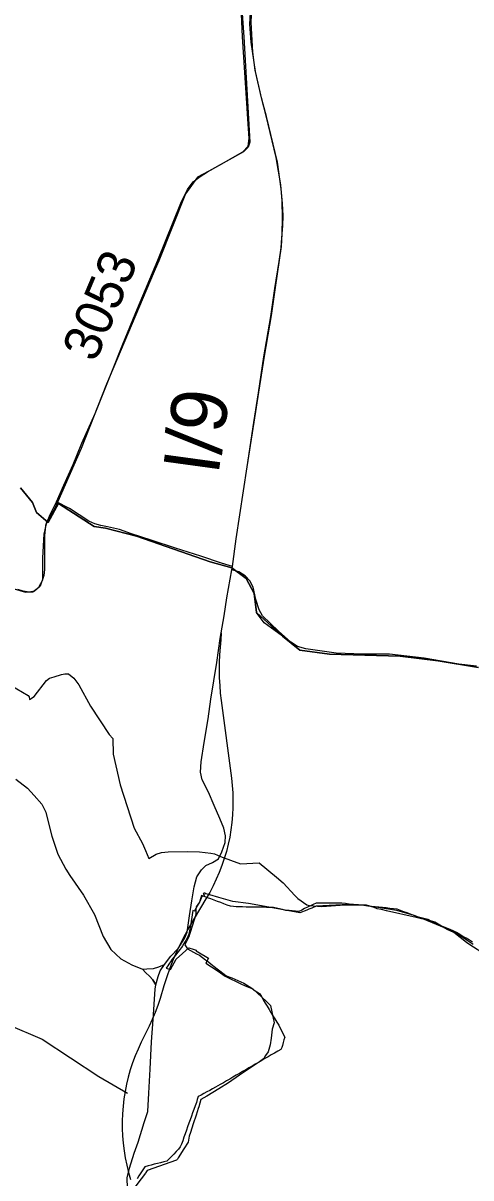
# Model space of a CAD drawing. Extents: x -789162 to -606354, y -1062736 to -945481.
# Drawn here: x -726966 to -725766, y -985051 to -981952 of the extents above; entities that cross this region are included whole.
import ezdxf

# ---------------------------------------------------------------- set-up
doc = ezdxf.new("R2010")
doc.units = 0
for name, color, linetype in [('_SIRSI VZTAHY CHKO HRANICE', 7, 'Continuous'), ('_SIRSI VZTAHY_CYKLOTRASY MISTNI S', 7, 'Continuous'), ('_SIRSI VZTAHY_CYKLOTRASY MISTNI_POPIS', 7, 'Continuous'), ('_SIRSI VZTAHY_NATURA_EVL', 7, 'Continuous'), ('_SIRSI VZTAHY_OP vodnich zdroju II stupne', 7, 'Continuous'), ('_SIRSI VZTAHY_SILNICE I TRIDY_NAVRH', 7, 'Continuous'), ('_SIRSI VZTAHY_SILNICE I TRIDY_STAV', 7, 'Continuous'), ('_SIRSI VZTAHY_SILNICE III TRIDY_STAV', 7, 'Continuous'), ('_SIRSI VZTAHY_SILNICE_STAV_POPIS', 7, 'Continuous')]:
    doc.layers.add(name, color=color, linetype=linetype)

msp = doc.modelspace()

# ---------------------------------------------------------------- linework, layer by layer
at = {"layer": '_SIRSI VZTAHY CHKO HRANICE'}
msp.add_lwpolyline([(-725726.8, -984451.8), (-725769.2, -984425.2), (-725778.1, -984418.6), (-725811.9, -984392.6), (-725829.7, -984384), (-725835.6, -984380.8), (-725862.4, -984364.8), (-725876.7, -984360.1), (-725890.2, -984357.2), (-725898.3, -984355.2), (-725912.6, -984351.8), (-725992.6, -984334), (-726005.6, -984330.9), (-726017.4, -984328.3), (-726025.6, -984325.4), (-726045.8, -984318.8), (-726067.4, -984317.5), (-726080.4, -984317), (-726093.1, -984317.2), (-726180.8, -984321.6), (-726192.3, -984326.6), (-726200, -984329.9), (-726206.2, -984332.6), (-726224.7, -984339.3), (-726288, -984327.7), (-726362.4, -984314.2), (-726404.5, -984309.4), (-726441.5, -984298.6), (-726466.1, -984291.2), (-726476.2, -984288.6), (-726478.9, -984286.5), (-726482.2, -984286.5), (-726482.3, -984286.6), (-726484, -984289.5), (-726480.4, -984290.8), (-726481.7, -984294.7), (-726481.7, -984294.7), (-726485.8, -984293.9), (-726485.9, -984294), (-726493.1, -984310.5), (-726506.9, -984334.4), (-726506.9, -984334.4), (-726506.9, -984334.5), (-726511.3, -984333.4), (-726511.8, -984333.3), (-726512.5, -984338.5), (-726514.3, -984351.1), (-726516, -984362.3), (-726517.9, -984375.4), (-726519.9, -984387.5), (-726522.2, -984396.3), (-726523.6, -984400.9), (-726525.6, -984404.7), (-726530.3, -984413.2), (-726533.7, -984419.2), (-726538.1, -984426.3), (-726539.2, -984428.1), (-726541.8, -984432.1), (-726546.4, -984437.6), (-726548.1, -984440.4), (-726561.6, -984457.5), (-726566.5, -984463.5), (-726569.4, -984468), (-726575.8, -984477.4), (-726578.6, -984481.4), (-726580.8, -984484.8), (-726582.8, -984487.9), (-726571.1, -984491.3), (-726555.6, -984463.8), (-726521.8, -984433.5), (-726510.3, -984437.2), (-726502, -984439.7), (-726502.7, -984440.9), (-726497.9, -984443.7), (-726469.8, -984460.8), (-726476.7, -984474.4), (-726443.9, -984496), (-726424.6, -984509.1), (-726381.1, -984531.2), (-726366.8, -984536.8), (-726350.8, -984543.4), (-726314.3, -984576.9), (-726302.8, -984587.8), (-726293.1, -984634.8), (-726298.3, -984651.8), (-726299.6, -984659.6), (-726301.4, -984675.4), (-726303.8, -984693.4), (-726309.8, -984712.1), (-726316.2, -984722.3), (-726321.2, -984730.6), (-726321.6, -984730.9), (-726332.9, -984738.7), (-726354.1, -984753.2), (-726386.1, -984775.1), (-726416.1, -984795.9), (-726442, -984811.6), (-726473.8, -984830.9), (-726489.5, -984840.4), (-726495.5, -984859.6), (-726497, -984864.2), (-726502.8, -984882.3), (-726510.3, -984905.6), (-726517.6, -984928.6), (-726520.8, -984939), (-726522.8, -984949.6), (-726524, -984955), (-726535.2, -984972.8), (-726550.4, -984996.3), (-726552.8, -985000.1), (-726555.2, -985003.2), (-726634.2, -985031.1), (-726637.1, -985035.9), (-726638.4, -985037.6), (-726676.1, -985086.8)], dxfattribs=at)
at = {"layer": '_SIRSI VZTAHY_CYKLOTRASY MISTNI S'}
for points in [[(-726381.6, -981889.3), (-726374.5, -981989.5), (-726358.6, -982272.2), (-726363.3, -982285.3), (-726375.7, -982298.1), (-726468.6, -982349.9), (-726498.5, -982365.5), (-726530.8, -982410.8), (-726602.7, -982590.6), (-726614.7, -982618.4), (-726742.4, -982921.4), (-726810.9, -983094), (-726873, -983236.1), (-726883.5, -983257.7), (-726902.3, -983289.5), (-726906, -983300.1), (-726908.7, -983327.7), (-726908.7, -983366.1), (-726909.2, -983418), (-726911, -983434.7), (-726920.5, -983463.4), (-726935.6, -983476.5), (-726950, -983479.2), (-726965.8, -983476.5), (-726980.3, -983471.8)], [(-726998.3, -983729.8), (-726953, -983756.6), (-726950.5, -983759.8), (-726948.8, -983767), (-726936.8, -983758.6), (-726903.9, -983715.7), (-726895.4, -983709.5), (-726882.9, -983706), (-726863, -983700), (-726854.8, -983698), (-726844.7, -983698), (-726830.5, -983709.6), (-726816.8, -983728), (-726785.7, -983785.1), (-726735.6, -983861.4), (-726725.4, -983871.5), (-726725.1, -983913.5), (-726717.8, -983944.9), (-726706, -983996.1), (-726668.9, -984112.3), (-726646.2, -984153.5), (-726638.3, -984172), (-726628.9, -984193.7), (-726609.8, -984181.9), (-726595.5, -984177.4), (-726577.8, -984175.4), (-726525.8, -984175.1), (-726493.8, -984176.1), (-726462.8, -984179.4), (-726453.5, -984181.2), (-726437.2, -984187.9), (-726383.8, -984207.7), (-726333.8, -984205.1), (-726287, -984243.9), (-726269, -984258.8), (-726238.2, -984292.6), (-726230.3, -984301.3), (-726206.2, -984318.1), (-726199.3, -984319.7), (-726166, -984322.2), (-726104.1, -984318), (-726056.8, -984318.1), (-726026.1, -984322.1), (-725976.2, -984330.1), (-725965.3, -984331.8), (-725918.6, -984345.8), (-725895.4, -984354.3), (-725822.6, -984384.6), (-725792.4, -984402.4), (-725760.2, -984423.9)]]:
    msp.add_lwpolyline(points, dxfattribs=at)
at = {"layer": '_SIRSI VZTAHY_NATURA_EVL'}
msp.add_line((-726235.9, -984334.8), (-726235.9, -984334.8), dxfattribs=at)
for points in [[(-726235.9, -984334.8), (-726244.7, -984334.2), (-726253.5, -984333.5), (-726262.3, -984332.9), (-726270.6, -984330.9), (-726278.8, -984329), (-726287.1, -984327.1), (-726295.4, -984325.1), (-726304.5, -984325), (-726313.7, -984324.8), (-726322.9, -984324.6), (-726332, -984324.4), (-726341.2, -984324.3), (-726350.4, -984324.1), (-726359.5, -984323.9), (-726368.7, -984323.8), (-726377.8, -984323.6), (-726387, -984323.4), (-726394.8, -984322.9), (-726402.6, -984322.3), (-726410.4, -984321.7), (-726419.2, -984318.4), (-726428, -984315.1), (-726436.7, -984311.9), (-726445.5, -984308.6), (-726454.2, -984305.3), (-726463, -984302), (-726471.7, -984298.8), (-726480.5, -984295.5), (-726481.2, -984295.2), (-726487.7, -984292.9), (-726490.5, -984301.9), (-726493.3, -984310.9), (-726498, -984317), (-726502.6, -984323), (-726503, -984330), (-726503.3, -984337), (-726503.6, -984343.9), (-726506.3, -984352.5), (-726509, -984361), (-726511.6, -984369.5), (-726514.3, -984378), (-726517, -984386.6), (-726519.6, -984395.1), (-726522.3, -984403.6), (-726525.7, -984410.9), (-726529.1, -984418.2), (-726532.5, -984425.6), (-726529.3, -984430.9), (-726526.1, -984436.2), (-726517.9, -984440.5), (-726509.6, -984444.8), (-726501.4, -984449), (-726493.1, -984453.2), (-726485.3, -984459.3), (-726477.6, -984465.3), (-726469.8, -984471.3), (-726462, -984477.3), (-726454.2, -984483.3), (-726446.4, -984489.3), (-726438.6, -984495.3), (-726430.8, -984501.3), (-726423.1, -984507.3), (-726414.9, -984510.7), (-726406.8, -984514.2), (-726398.7, -984517.6), (-726390.6, -984521), (-726382.5, -984524.4), (-726374.4, -984527.9), (-726367.4, -984532.5), (-726360.5, -984537.2), (-726353.6, -984541.8), (-726346.7, -984546.5), (-726339.7, -984551.2), (-726332.8, -984555.8), (-726327.7, -984564.3), (-726322.5, -984572.9), (-726317.3, -984581.4), (-726312.2, -984589.9), (-726307, -984598.4), (-726301.9, -984607), (-726296.7, -984615.5), (-726291.6, -984624), (-726286.4, -984632.5), (-726281.2, -984641.1), (-726277.2, -984649.1), (-726273.2, -984657.2), (-726269.2, -984665.2), (-726265.1, -984673.3), (-726267, -984680.5), (-726268.9, -984687.7), (-726270.8, -984694.9), (-726273.1, -984700.3), (-726275.4, -984705.7), (-726283.9, -984710.7), (-726292.5, -984715.6), (-726301.1, -984720.6), (-726309.6, -984725.6), (-726318.2, -984730.5), (-726326.8, -984735.5), (-726335.3, -984740.5), (-726343.9, -984745.5), (-726352.4, -984750.4), (-726361, -984755.4), (-726369.6, -984760.4), (-726378.1, -984765.3), (-726386.7, -984770.3), (-726395.2, -984775.3), (-726403.8, -984780.2), (-726412.4, -984785.2), (-726420.9, -984790.2), (-726429.5, -984795.2), (-726438.1, -984800.1), (-726444.2, -984803.7), (-726450.4, -984807.2), (-726458.2, -984811.4), (-726466, -984815.6), (-726473.8, -984819.8), (-726481.6, -984824.1), (-726489.4, -984828.3), (-726497.2, -984832.5), (-726499.6, -984840.2), (-726501.9, -984847.9), (-726505.3, -984857.2), (-726508.6, -984866.6), (-726511.9, -984875.9), (-726515.3, -984885.3), (-726518.6, -984894.6), (-726521.9, -984904), (-726525.3, -984913.4), (-726528.6, -984922.7), (-726531.9, -984932.1), (-726535.3, -984941.4), (-726538.6, -984950.8), (-726541.9, -984960.1), (-726545.7, -984966.9), (-726549.4, -984973.8), (-726555.7, -984980.1), (-726562.1, -984986.4), (-726568.4, -984992.7), (-726574.7, -984999.1), (-726581.1, -985005.4), (-726589.5, -985007.5), (-726597.9, -985009.7), (-726606.3, -985011.8), (-726614.7, -985013.9), (-726623.1, -985016.1), (-726631.5, -985018.2), (-726639.9, -985020.4), (-726645.1, -985028.6), (-726650.4, -985036.8), (-726655.7, -985045.1), (-726660.9, -985053.3)], [(-725761.6, -984417.7), (-725770.2, -984412.7), (-725778.8, -984407.6), (-725787.4, -984402.6), (-725796, -984397.5), (-725804.6, -984392.4), (-725813.2, -984387.4), (-725821.9, -984384), (-725830.6, -984380.7), (-725839.4, -984377.3), (-725848.1, -984374), (-725856.8, -984370.6), (-725864.9, -984366.1), (-725872.9, -984361.7), (-725880.9, -984357.2), (-725888.3, -984355.4), (-725895.6, -984353.6), (-725903, -984351.8), (-725910.3, -984350.1), (-725919.2, -984346.6), (-725928.1, -984343.2), (-725937, -984339.8), (-725945.9, -984336.4), (-725954.8, -984333), (-725963.7, -984329.6), (-725973.6, -984328.5), (-725983.4, -984327.4), (-725993.3, -984326.4), (-726003.2, -984325.3), (-726013.1, -984324.2), (-726022.9, -984323.2), (-726032.8, -984322.1), (-726042.7, -984321.1), (-726052.6, -984320), (-726062.4, -984318.9), (-726072.3, -984317.9), (-726082.2, -984316.8), (-726092.1, -984315.8), (-726101.9, -984314.7), (-726111.8, -984313.6), (-726121.7, -984313.6), (-726131.6, -984313.6), (-726141.5, -984313.6), (-726151.3, -984313.6), (-726161.2, -984313.6), (-726171.1, -984313.6), (-726181, -984313.6), (-726188.7, -984317.3), (-726196.4, -984320.9), (-726204, -984324.6), (-726211.7, -984328.2), (-726219.4, -984331.9), (-726227.1, -984335.5), (-726235.9, -984334.8)]]:
    msp.add_lwpolyline(points, dxfattribs=at)
at = {"layer": '_SIRSI VZTAHY_OP vodnich zdroju II stupne'}
for points in [[(-726973.1, -983199.3), (-726941.4, -983239), (-726930.8, -983265.4), (-726899.1, -983291.9), (-726871.3, -983241.6), (-726776, -983302.5), (-726745.6, -983307.8), (-726662.3, -983328.9), (-726465.1, -983397.7), (-726406.9, -983413.6), (-726368.6, -983442.7), (-726347.4, -983482.4), (-726340.8, -983534), (-726270.7, -983597.5), (-726224.4, -983634.5), (-726145, -983645.1), (-725955.8, -983650.4), (-725854, -983663.6), (-725745.5, -983680.8)], [(-725745.5, -983680.8), (-725854, -983663.6), (-725955.8, -983650.4), (-726145, -983645.1), (-726224.4, -983634.5), (-726270.7, -983597.5), (-726320.1, -983561.2), (-726340.8, -983534), (-726347.4, -983482.4), (-726368.6, -983442.7), (-726406.9, -983413.6), (-726465.1, -983397.7), (-726662.3, -983328.9), (-726745.6, -983307.8), (-726776, -983302.5), (-726871.3, -983241.6), (-726899.1, -983291.9), (-726930.8, -983265.4), (-726941.4, -983239), (-726973.1, -983199.3)]]:
    msp.add_lwpolyline(points, dxfattribs=at)
at = {"layer": '_SIRSI VZTAHY_SILNICE I TRIDY_NAVRH'}
for points in [[(-729292.6, -983206.3), (-729195.2, -983297.2), (-729139.8, -983345.6), (-729077.2, -983390.5), (-728914.4, -983460.7), (-728779.2, -983513.2), (-728675.8, -983576.6), (-728616.2, -983623.4), (-728558.4, -983676.7), (-728506.6, -983744.7), (-728437.5, -983843.7), (-728331.8, -983983.2), (-728240.3, -984081.8), (-728136.9, -984176.6), (-727947.2, -984313.2), (-727811.6, -984385.5), (-727689, -984437.2), (-727416.2, -984524.4), (-727092.7, -984615.9), (-727007.4, -984639.2), (-726915.2, -984677.9), (-726763.5, -984778.1), (-726686.8, -984823.4)], [(-726435.2, -983588), (-726436.1, -983606.7), (-726438.3, -983627), (-726439.8, -983647.5), (-726440.7, -983667.9), (-726440.9, -983688.4), (-726440.5, -983708.9), (-726439.4, -983729.3), (-726437.7, -983749.8), (-726435.4, -983770.1), (-726408.1, -983977.7), (-726405.9, -983997.5), (-726404.5, -984017.3), (-726403.8, -984037.2), (-726404, -984057), (-726404.9, -984076.9), (-726406.7, -984096.7), (-726409.2, -984116.4), (-726412.5, -984136), (-726416.6, -984155.4), (-726421.5, -984174.7), (-726427.1, -984193.7), (-726433.4, -984212.5), (-726440.5, -984231.1), (-726448.4, -984249.3), (-726456.9, -984267.3), (-726466.2, -984284.9), (-726476.2, -984302), (-726507.8, -984354.3), (-726520.4, -984375.7), (-726532.2, -984397.5), (-726543.4, -984419.7), (-726553.9, -984442.2), (-726563.7, -984465), (-726572.7, -984488.1), (-726581.1, -984511.5), (-726588.7, -984535.1), (-726599.2, -984569.4), (-726605.4, -984588.3), (-726612.3, -984606.9), (-726620, -984625.3), (-726628.4, -984643.3), (-726649.7, -984686.8), (-726658.1, -984704.9), (-726665.8, -984723.2), (-726672.7, -984741.9), (-726678.9, -984760.8), (-726684.3, -984780), (-726689, -984799.3), (-726692.9, -984818.9), (-726696, -984838.5), (-726698.3, -984858.3), (-726699.8, -984878.2), (-726700.6, -984898.1), (-726700.5, -984918), (-726699.7, -984937.9), (-726698, -984957.7), (-726695.6, -984977.5), (-726692.4, -984997.1), (-726688.4, -985016.6), (-726683.7, -985036), (-726678.1, -985055.1)]]:
    msp.add_lwpolyline(points, dxfattribs=at)
at = {"layer": '_SIRSI VZTAHY_SILNICE I TRIDY_STAV'}
for points in [[(-726404.9, -983410.4), (-726395.3, -983335.7), (-726365.5, -983142.5), (-726347.1, -983023), (-726334.4, -982942.9), (-726319.2, -982846), (-726300.9, -982737.1), (-726289.4, -982662.1), (-726274.1, -982551.9), (-726272.2, -982517.4), (-726270.9, -982475.1), (-726271.5, -982429.6), (-726275.4, -982386.6), (-726287.8, -982313.1), (-726315.2, -982201.5), (-726327.1, -982152.5), (-726344, -982078.4), (-726350.3, -982030.8), (-726355.3, -981951), (-726352.2, -981886), (-726350.4, -981858.3)], [(-726404.9, -983410.4), (-726395.4, -983336), (-726366.1, -983143.3), (-726348.1, -983024.2), (-726335.6, -982944.3), (-726320.6, -982847.7), (-726302.5, -982739.2), (-726291.3, -982664.3), (-726279.5, -982592), (-726275, -982555.4), (-726272.7, -982528.6), (-726270.4, -982496.3), (-726269.1, -982468.6), (-726271.3, -982436.5), (-726274.3, -982397.1), (-726284.1, -982325.3), (-726313.5, -982202.9), (-726326, -982156.1), (-726343.7, -982082.5), (-726354.9, -982003.3), (-726358.4, -981955.7), (-726355.4, -981890.9)], [(-726587.3, -984478.3), (-726570.4, -984456), (-726550.9, -984434.8), (-726533.7, -984408.5), (-726526.5, -984390.9), (-726520.1, -984347.8), (-726514, -984306.9), (-726508.2, -984269.6), (-726500.6, -984243.2), (-726488.2, -984223.9), (-726476.5, -984212.3), (-726458.5, -984204.1), (-726442.7, -984194.5), (-726433.9, -984175.3), (-726425.1, -984150.6), (-726423.9, -984132.7), (-726427.9, -984111.9), (-726439.1, -984086.4), (-726454.3, -984051.6), (-726469.8, -984016.1), (-726486.2, -983982.6), (-726490.6, -983961.8), (-726488.6, -983933.9), (-726480.6, -983882), (-726470.6, -983819.3), (-726463.1, -983766.3), (-726447.1, -983668.1), (-726437.9, -983603.5), (-726427.3, -983542.4), (-726420.2, -983493.9), (-726406.5, -983419.5)], [(-726587.3, -984478.3), (-726570.4, -984456), (-726550.9, -984434.8), (-726533.7, -984408.5), (-726526.5, -984390.9), (-726520.1, -984347.8), (-726514, -984306.9), (-726508.2, -984269.6), (-726500.6, -984243.2), (-726488.2, -984223.9), (-726476.5, -984212.3), (-726458.5, -984204.1), (-726442.7, -984194.5), (-726433.9, -984175.3), (-726425.1, -984150.6), (-726423.9, -984132.7), (-726427.9, -984111.9), (-726439.1, -984086.4), (-726454.3, -984051.6), (-726469.8, -984016.1), (-726486.2, -983982.6), (-726490.6, -983961.8), (-726488.6, -983933.9), (-726480.6, -983882), (-726470.6, -983819.3), (-726463.1, -983766.3), (-726447.1, -983668.1), (-726437.9, -983603.5), (-726427.3, -983542.4), (-726420.2, -983493.9), (-726406.5, -983419.5)], [(-726406.5, -983419.5), (-726404.9, -983410.4)], [(-726406.5, -983419.5), (-726404.9, -983410.4)], [(-726986.1, -983980.8), (-726954.7, -984004.8), (-726936.7, -984024.2), (-726915.7, -984048.2), (-726905.5, -984069.4), (-726899, -984095.2), (-726889.5, -984133.5), (-726879.4, -984163.2), (-726873.2, -984182.2), (-726851.7, -984221.8), (-726840.7, -984239.2), (-726804.7, -984292.2), (-726774.6, -984343.6), (-726751.5, -984402.8), (-726731.2, -984438.2), (-726704.7, -984463.2), (-726675.1, -984478.8), (-726646.5, -984490.7)], [(-726986.1, -983980.8), (-726954.7, -984004.8), (-726936.7, -984024.2), (-726915.7, -984048.2), (-726905.5, -984069.4), (-726899, -984095.2), (-726889.5, -984133.5), (-726879.4, -984163.2), (-726873.2, -984182.2), (-726851.7, -984221.8), (-726840.7, -984239.2), (-726804.7, -984292.2), (-726774.6, -984343.6), (-726751.5, -984402.8), (-726731.2, -984438.2), (-726704.7, -984463.2), (-726675.1, -984478.8), (-726646.5, -984490.7)], [(-726610.2, -984532.8), (-726618.9, -984519.5), (-726627.4, -984509.2), (-726637, -984500.6), (-726646.5, -984490.7), (-726634.3, -984489.4), (-726616.5, -984489.1), (-726602.6, -984483.9), (-726587.3, -984478.3)], [(-726646.5, -984490.7), (-726634.3, -984489.4), (-726616.5, -984489.1), (-726602.6, -984483.9), (-726587.3, -984478.3)], [(-726610.2, -984532.8), (-726604.6, -984509.8), (-726598.9, -984495.2), (-726587.3, -984478.3)], [(-726610.2, -984532.8), (-726604.6, -984509.8), (-726598.9, -984495.2), (-726587.3, -984478.3)], [(-726646.5, -984490.7), (-726637, -984500.6), (-726627.4, -984509.2), (-726618.9, -984519.5), (-726610.2, -984532.8)], [(-726686.4, -985078.5), (-726687.5, -985050.4), (-726681.2, -985024.5), (-726668.6, -984984.3), (-726657.7, -984955), (-726641.6, -984902.2), (-726632.4, -984872.3), (-726629, -984822.9), (-726625.5, -984759.2), (-726622.6, -984685.1), (-726617.6, -984625.3), (-726612.5, -984543.8), (-726610.2, -984532.8)], [(-726686.4, -985078.5), (-726687.5, -985050.4), (-726681.2, -985024.5), (-726668.6, -984984.3), (-726657.7, -984955), (-726641.6, -984902.2), (-726632.4, -984872.3), (-726629, -984822.9), (-726625.5, -984759.2), (-726622.6, -984685.1), (-726617.6, -984625.3), (-726612.5, -984543.8), (-726610.2, -984532.8)]]:
    msp.add_lwpolyline(points, dxfattribs=at)
at = {"layer": '_SIRSI VZTAHY_SILNICE III TRIDY_STAV'}
for points in [[(-726876.9, -983237.2), (-726857, -983192.3), (-726832.5, -983136.7), (-726808.5, -983079.6), (-726773.2, -983000.1), (-726730.4, -982892.3), (-726699.3, -982813.8), (-726659.5, -982718.4), (-726605.4, -982588.8), (-726543.2, -982435.2), (-726525.3, -982399), (-726510.6, -982378.1), (-726492.1, -982364.1), (-726471.9, -982351.1), (-726441.4, -982334.6), (-726376.9, -982298), (-726363.1, -982282.2), (-726360, -982262.3), (-726364.1, -982209.2), (-726366.2, -982166.9), (-726377.9, -981989.3), (-726382.9, -981885.1)], [(-726990.6, -983469.9), (-726960, -983479.1), (-726939.8, -983478.5), (-726923.9, -983466), (-726913.8, -983445.9), (-726913.1, -983420.9), (-726913.8, -983386.7), (-726910.1, -983323.5), (-726902.3, -983292.1), (-726892.7, -983269.4), (-726876.9, -983237.2)], [(-726404.9, -983410.4), (-726434.2, -983400.9), (-726489.8, -983382.8), (-726557.7, -983361.2), (-726623.3, -983339.9), (-726675.6, -983322.8), (-726708.1, -983311), (-726739.7, -983303.4), (-726757.8, -983300.7), (-726774.4, -983296), (-726790.4, -983288.5), (-726842, -983254.4), (-726876.9, -983237.2)], [(-725750.9, -983677.2), (-725798.2, -983671.9), (-725891.2, -983656.2), (-725984.1, -983645.3), (-726055.4, -983645.5), (-726127.1, -983642.4), (-726208.2, -983631.3), (-726230.4, -983625.1), (-726248.8, -983613.2), (-726282.1, -983584.1), (-726325, -983542.3), (-726333.4, -983526.9), (-726342.6, -983499.2), (-726349.4, -983466.1), (-726358.4, -983448.6), (-726371, -983435.7), (-726387.9, -983424.3), (-726406.5, -983419.5)]]:
    msp.add_lwpolyline(points, dxfattribs=at)

# ---------------------------------------------------------------- texts
at = {"layer": '_SIRSI VZTAHY_CYKLOTRASY MISTNI_POPIS'}
msp.add_text('3053', height=100, rotation=67.1442, dxfattribs=at).set_placement((-726772.6, -982865.2))
at = {"layer": '_SIRSI VZTAHY_SILNICE_STAV_POPIS'}
msp.add_text('I/9', height=150, rotation=82.1982, dxfattribs=at).set_placement((-726443, -983167.4))

doc.saveas('drawing.dxf')
